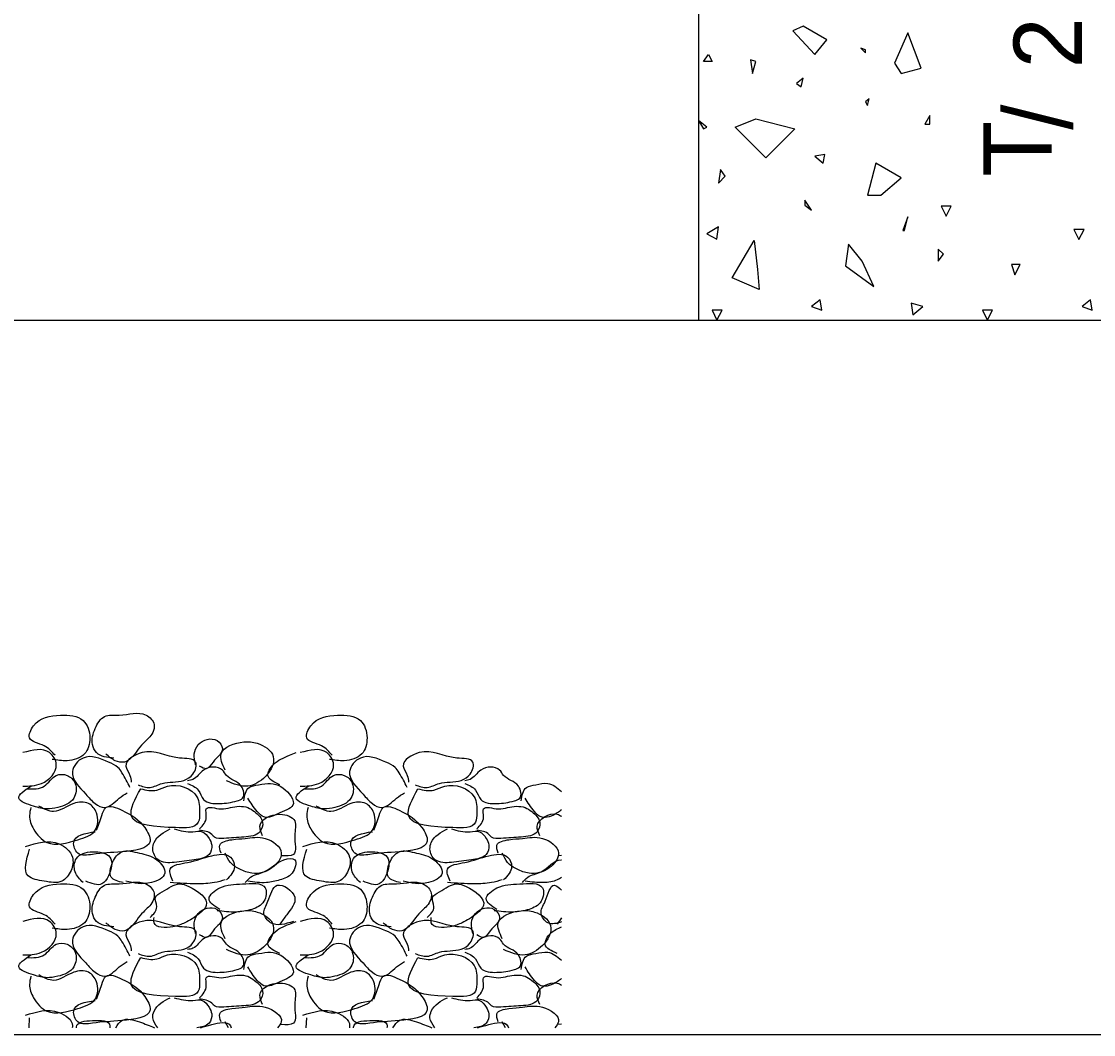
# Model space of a CAD drawing. Extents: x 2.92 to 10.05, y 1.3 to 10.63.
# Drawn here: x 5.007 to 5.949, y 5.922 to 6.811 of the extents above; entities that cross this region are included whole.
import ezdxf

# ---------------------------------------------------------------- set-up
doc = ezdxf.new("R2010")
doc.units = 0
for name, color, linetype in [('DETL-LINE', 7, 'Continuous'), ('DETL-NOTE', 7, 'Continuous'), ('DETL-PATT', 7, 'Continuous')]:
    doc.layers.add(name, color=color, linetype=linetype)

msp = doc.modelspace()

# ---------------------------------------------------------------- linework, layer by layer
at = {"layer": 'DETL-LINE'}
for p, q in [((5.60141, 7.37627), (5.60141, 6.54902)), ((3.60141, 6.54902), (7.87612, 6.54902)), ((3.60141, 5.92157), (7.87612, 5.92157))]:
    msp.add_line(p, q, dxfattribs=at)
at = {"layer": 'DETL-PATT'}
for p, q in [((5.48133, 6.0789), (5.47859, 6.07859)), ((5.48133, 6.02408), (5.47741, 6.01859)), ((5.01345, 5.92761), (5.01388, 5.93624)), ((5.25698, 5.92761), (5.25741, 5.93624)), ((5.18855, 5.92761), (5.18565, 5.93271)), ((5.43208, 5.92761), (5.42918, 5.93271)), ((5.48133, 5.93067), (5.47859, 5.93035))]:
    msp.add_line(p, q, dxfattribs=at)
for points in [[(5.68435, 6.80314), (5.70376, 6.78231), (5.71435, 6.79537), (5.69353, 6.80737)], [(5.77965, 6.76573), (5.79729, 6.77031), (5.78529, 6.80137), (5.77365, 6.7749)], [(5.61024, 6.78231), (5.61341, 6.77631), (5.606, 6.77631)], [(5.74824, 6.78655), (5.744, 6.78796), (5.74824, 6.78373)], [(5.64729, 6.77773), (5.64906, 6.76573), (5.65188, 6.77631)], [(5.68753, 6.7569), (5.69176, 6.75408), (5.69353, 6.76149)], [(5.75141, 6.74349), (5.74824, 6.74067), (5.75, 6.73749)], [(5.65188, 6.72584), (5.68612, 6.71702), (5.66071, 6.69161), (5.63388, 6.71843)], [(5.80471, 6.72867), (5.80047, 6.72125), (5.80471, 6.72125)], [(5.70376, 6.69302), (5.71118, 6.68702), (5.71259, 6.69443)], [(5.76165, 6.65878), (5.77965, 6.67396), (5.75741, 6.68702), (5.75, 6.65878)], [(5.62082, 6.68137), (5.61906, 6.66937), (5.62506, 6.67537)], [(5.69494, 6.65455), (5.69494, 6.64996), (5.70094, 6.64573)], [(5.81473, 6.64912), (5.81897, 6.64029), (5.82356, 6.64912)], [(5.60882, 6.6249), (5.61765, 6.62031), (5.61906, 6.6309)], [(5.78106, 6.62773), (5.78247, 6.62773), (5.78529, 6.63973)], [(5.93139, 6.62876), (5.93563, 6.61994), (5.94022, 6.62876)], [(5.65329, 6.59349), (5.65471, 6.57584), (5.63106, 6.58608), (5.65047, 6.6189)], [(5.73341, 6.61573), (5.73059, 6.59667), (5.75565, 6.57867), (5.74541, 6.6009)], [(5.81212, 6.61149), (5.81212, 6.6009), (5.81671, 6.6069)], [(5.87658, 6.59781), (5.8794, 6.58899), (5.88399, 6.59781)], [(5.70835, 6.56702), (5.70094, 6.56102), (5.70976, 6.55784)], [(5.94588, 6.56702), (5.93847, 6.56102), (5.94729, 6.55784)], [(5.78847, 6.56384), (5.78988, 6.55361), (5.79871, 6.56102)]]:
    msp.add_lwpolyline(points, close=True, dxfattribs=at)
for points in [[(5.60141, 6.72443), (5.606, 6.71702), (5.60882, 6.71843), (5.60141, 6.72443)], [(5.61765, 6.54902), (5.62224, 6.55784), (5.61341, 6.55784), (5.61765, 6.54902)], [(5.85533, 6.54929), (5.85976, 6.55784), (5.85094, 6.55784), (5.85506, 6.54929)]]:
    msp.add_lwpolyline(points, dxfattribs=at)
for points in [[(5.03624, 6.16682), (5.02682, 6.17506), (5.01388, 6.18212), (5.01741, 6.19271), (5.04094, 6.20212), (5.06094, 6.19741), (5.06682, 6.18212), (5.06212, 6.168), (5.04682, 6.16212), (5.03388, 6.16329)], [(5.088, 6.16447), (5.07271, 6.16918), (5.06918, 6.17624), (5.07153, 6.19035), (5.07976, 6.20094), (5.09271, 6.20212), (5.11624, 6.20212), (5.12329, 6.19388), (5.12212, 6.18682), (5.11388, 6.17741), (5.108, 6.17035), (5.09741, 6.16094), (5.08918, 6.16212), (5.08094, 6.168)], [(5.27976, 6.16682), (5.27035, 6.17506), (5.25741, 6.18212), (5.26094, 6.19271), (5.28447, 6.20212), (5.30447, 6.19741), (5.31035, 6.18212), (5.30565, 6.168), (5.29035, 6.16212), (5.27741, 6.16329)], [(5.15976, 6.15859), (5.15859, 6.168), (5.16212, 6.17624), (5.17859, 6.17976), (5.18329, 6.17271), (5.17506, 6.16094), (5.16918, 6.15506), (5.16329, 6.15741)], [(5.18565, 6.15388), (5.18212, 6.168), (5.20212, 6.17859), (5.21388, 6.17741), (5.228, 6.16565), (5.22682, 6.15624), (5.22094, 6.148), (5.20565, 6.13976), (5.18682, 6.14447)], [(5.008, 6.13976), (5.02447, 6.14212), (5.03741, 6.15859), (5.03153, 6.16918), (5.008, 6.16918)], [(5.10918, 6.14094), (5.11976, 6.13859), (5.13035, 6.14212), (5.13976, 6.14329), (5.15741, 6.15035), (5.15976, 6.16094), (5.14565, 6.16447), (5.11271, 6.16918), (5.09859, 6.15741), (5.10212, 6.14918), (5.10329, 6.14329)], [(5.23388, 6.14094), (5.22329, 6.14918), (5.228, 6.15859), (5.24212, 6.16682), (5.248, 6.16918)], [(5.25153, 6.13976), (5.268, 6.14212), (5.28094, 6.15859), (5.27506, 6.16918), (5.25153, 6.16918)], [(5.35271, 6.14094), (5.36329, 6.13859), (5.37388, 6.14212), (5.38329, 6.14329), (5.40094, 6.15035), (5.40329, 6.16094), (5.38918, 6.16447), (5.35624, 6.16918), (5.34212, 6.15741), (5.34565, 6.14918), (5.34682, 6.14329)], [(5.10212, 6.13859), (5.09506, 6.15153), (5.09153, 6.15624), (5.08329, 6.16094), (5.06094, 6.16447), (5.05153, 6.15271), (5.06329, 6.13271), (5.07153, 6.12447), (5.07976, 6.12094), (5.09271, 6.12918), (5.09976, 6.13388)], [(5.34565, 6.13859), (5.33859, 6.15153), (5.33506, 6.15624), (5.32682, 6.16094), (5.30447, 6.16447), (5.29506, 6.15271), (5.30682, 6.13271), (5.31506, 6.12447), (5.32329, 6.12094), (5.33624, 6.12918), (5.34329, 6.13388)], [(5.01153, 6.13741), (5.02682, 6.13976), (5.03741, 6.14918), (5.04682, 6.14918), (5.05388, 6.14212), (5.05271, 6.12918), (5.03859, 6.12094), (5.02918, 6.11976), (5.01741, 6.12212), (5.00447, 6.12918), (5.01506, 6.13976)], [(5.15271, 6.14212), (5.16212, 6.13624), (5.16682, 6.128), (5.18094, 6.12447), (5.19624, 6.12682), (5.20094, 6.12918), (5.19976, 6.13976), (5.18682, 6.14918), (5.18329, 6.15388), (5.16682, 6.15388), (5.15741, 6.14565), (5.15271, 6.14447)], [(5.25506, 6.13741), (5.27035, 6.13976), (5.28094, 6.14918), (5.29035, 6.14918), (5.29741, 6.14212), (5.29624, 6.12918), (5.28212, 6.12094), (5.27271, 6.11976), (5.26094, 6.12212), (5.248, 6.12918), (5.25859, 6.13976)], [(5.39624, 6.14212), (5.40565, 6.13624), (5.41035, 6.128), (5.42447, 6.12447), (5.43976, 6.12682), (5.44447, 6.12918), (5.44329, 6.13976), (5.43035, 6.14918), (5.42682, 6.15388), (5.41035, 6.15388), (5.40094, 6.14565), (5.39624, 6.14447)], [(5.11153, 6.13741), (5.10329, 6.11388), (5.14212, 6.10329), (5.16212, 6.108), (5.16329, 6.11624), (5.16094, 6.13035), (5.13506, 6.13976), (5.12565, 6.13624), (5.11153, 6.13741)], [(5.20212, 6.12682), (5.20682, 6.13859), (5.21506, 6.14094), (5.22565, 6.14212), (5.24212, 6.13271), (5.24565, 6.12447), (5.23388, 6.11624), (5.21976, 6.11271), (5.21388, 6.11741), (5.20565, 6.12918)], [(5.35506, 6.13741), (5.34682, 6.11388), (5.38565, 6.10329), (5.40565, 6.108), (5.40682, 6.11624), (5.40447, 6.13035), (5.37859, 6.13976), (5.36918, 6.13624), (5.35506, 6.13741)], [(5.44565, 6.12682), (5.45035, 6.13859), (5.45859, 6.14094), (5.46918, 6.14212), (5.48133, 6.13518)], [(5.01506, 6.12094), (5.01388, 6.11388), (5.01741, 6.10212), (5.02918, 6.09035), (5.05624, 6.09271), (5.07153, 6.10094), (5.07271, 6.11624), (5.06565, 6.12447), (5.05271, 6.12447), (5.03506, 6.11741), (5.02212, 6.12212)], [(5.07271, 6.10094), (5.07741, 6.11388), (5.08094, 6.12094), (5.09506, 6.11859), (5.11506, 6.10329), (5.11976, 6.09153), (5.09506, 6.08212), (5.06918, 6.07976), (5.05624, 6.08094), (5.05271, 6.09035), (5.07153, 6.09976)], [(5.16329, 6.10212), (5.16918, 6.11271), (5.16918, 6.11976), (5.18212, 6.11976), (5.19035, 6.12094), (5.20565, 6.12094), (5.21153, 6.11741), (5.21859, 6.108), (5.21624, 6.09976), (5.21035, 6.09624), (5.20212, 6.09506), (5.18447, 6.09388), (5.17624, 6.09506), (5.17388, 6.09741), (5.16329, 6.10094)], [(5.25859, 6.12094), (5.25741, 6.11388), (5.26094, 6.10212), (5.27271, 6.09035), (5.29976, 6.09271), (5.31506, 6.10094), (5.31624, 6.11624), (5.30918, 6.12447), (5.29624, 6.12447), (5.27859, 6.11741), (5.26565, 6.12212)], [(5.31624, 6.10094), (5.32094, 6.11388), (5.32447, 6.12094), (5.33859, 6.11859), (5.35859, 6.10329), (5.36329, 6.09153), (5.33859, 6.08212), (5.31271, 6.07976), (5.29976, 6.08094), (5.29624, 6.09035), (5.31506, 6.09976)], [(5.40682, 6.10212), (5.41271, 6.11271), (5.41271, 6.11976), (5.42565, 6.11976), (5.43388, 6.12094), (5.44918, 6.12094), (5.45506, 6.11741), (5.46212, 6.108), (5.45976, 6.09976), (5.45388, 6.09624), (5.44565, 6.09506), (5.428, 6.09388), (5.41976, 6.09506), (5.41741, 6.09741), (5.40682, 6.10094)], [(5.48133, 6.11898), (5.47741, 6.11624), (5.46329, 6.11271), (5.45741, 6.11741), (5.44918, 6.12918)], [(5.21859, 6.09624), (5.21624, 6.10447), (5.23388, 6.11506), (5.24682, 6.10918), (5.24682, 6.09624), (5.24565, 6.07976), (5.23506, 6.07859)], [(5.46212, 6.09624), (5.45976, 6.10447), (5.47741, 6.11506), (5.48133, 6.11329)], [(5.14094, 6.10212), (5.15741, 6.09976), (5.16565, 6.09976), (5.17153, 6.09388), (5.17388, 6.088), (5.17153, 6.07976), (5.15859, 6.07506), (5.14094, 6.07271), (5.12682, 6.07506), (5.12212, 6.08447), (5.12329, 6.09035), (5.12918, 6.09741), (5.13741, 6.10212)], [(5.18212, 6.08094), (5.18094, 6.088), (5.19153, 6.09271), (5.20329, 6.09388), (5.22094, 6.09388), (5.23506, 6.08094), (5.22682, 6.068), (5.20918, 6.06329), (5.19859, 6.06682), (5.19035, 6.07271), (5.18565, 6.08094)], [(5.38447, 6.10212), (5.40094, 6.09976), (5.40918, 6.09976), (5.41506, 6.09388), (5.41741, 6.088), (5.41506, 6.07976), (5.40212, 6.07506), (5.38447, 6.07271), (5.37035, 6.07506), (5.36565, 6.08447), (5.36682, 6.09035), (5.37271, 6.09741), (5.38094, 6.10212)], [(5.42565, 6.08094), (5.42447, 6.088), (5.43506, 6.09271), (5.44682, 6.09388), (5.46447, 6.09388), (5.47859, 6.08094), (5.47035, 6.068), (5.45271, 6.06329), (5.44212, 6.06682), (5.43388, 6.07271), (5.42918, 6.08094)], [(5.01035, 6.08682), (5.03976, 6.08918), (5.05153, 6.07741), (5.05035, 6.06565), (5.04212, 6.05624), (5.02682, 6.05624), (5.01271, 6.06094), (5.01388, 6.08447)], [(5.25388, 6.08682), (5.28329, 6.08918), (5.29506, 6.07741), (5.29388, 6.06565), (5.28565, 6.05624), (5.27035, 6.05624), (5.25624, 6.06094), (5.25741, 6.08447)], [(5.06094, 6.05506), (5.05388, 6.06447), (5.05506, 6.07624), (5.06918, 6.08212), (5.08447, 6.07741), (5.08329, 6.06094), (5.07741, 6.05388), (5.06329, 6.05624)], [(5.09624, 6.05506), (5.08565, 6.05976), (5.08682, 6.07271), (5.09506, 6.08212), (5.11035, 6.08094), (5.12565, 6.07506), (5.13271, 6.06329), (5.12094, 6.05506), (5.09859, 6.05624)], [(5.13976, 6.05624), (5.13741, 6.06682), (5.15271, 6.07271), (5.17388, 6.07859), (5.19035, 6.07741), (5.19388, 6.06918), (5.18682, 6.05741)], [(5.20329, 6.05506), (5.208, 6.05976), (5.21976, 6.06447), (5.23741, 6.07506), (5.24682, 6.07506), (5.24447, 6.06329), (5.23388, 6.05741), (5.22212, 6.05506), (5.20565, 6.05624)], [(5.30447, 6.05506), (5.29741, 6.06447), (5.29859, 6.07624), (5.31271, 6.08212), (5.328, 6.07741), (5.32682, 6.06094), (5.32094, 6.05388), (5.30682, 6.05624)], [(5.33976, 6.05506), (5.32918, 6.05976), (5.33035, 6.07271), (5.33859, 6.08212), (5.35388, 6.08094), (5.36918, 6.07506), (5.37624, 6.06329), (5.36447, 6.05506), (5.34212, 6.05624)], [(5.38329, 6.05624), (5.38094, 6.06682), (5.39624, 6.07271), (5.41741, 6.07859), (5.43388, 6.07741), (5.43741, 6.06918), (5.43035, 6.05741)], [(5.44682, 6.05506), (5.45153, 6.05976), (5.46329, 6.06447), (5.48094, 6.07506), (5.48133, 6.07506)], [(5.088, 6.01624), (5.07271, 6.02094), (5.06918, 6.028), (5.07153, 6.04212), (5.07976, 6.05271), (5.09271, 6.05388), (5.11624, 6.05388), (5.12329, 6.04565), (5.12212, 6.03859), (5.11388, 6.02918), (5.108, 6.02212), (5.09741, 6.01271), (5.08918, 6.01388), (5.08094, 6.01976)], [(5.18565, 6.05741), (5.17624, 6.05506), (5.16094, 6.05388), (5.13741, 6.05506)], [(5.33153, 6.01624), (5.31624, 6.02094), (5.31271, 6.028), (5.31506, 6.04212), (5.32329, 6.05271), (5.33624, 6.05388), (5.35976, 6.05388), (5.36682, 6.04565), (5.36565, 6.03859), (5.35741, 6.02918), (5.35153, 6.02212), (5.34094, 6.01271), (5.33271, 6.01388), (5.32447, 6.01976)], [(5.42918, 6.05741), (5.41976, 6.05506), (5.40447, 6.05388), (5.38094, 6.05506)], [(5.48133, 6.05961), (5.47741, 6.05741), (5.46565, 6.05506), (5.44918, 6.05624)], [(5.03624, 6.01859), (5.02682, 6.02682), (5.01388, 6.03388), (5.01741, 6.04447), (5.04094, 6.05388), (5.06094, 6.04918), (5.06682, 6.03388), (5.06212, 6.01976), (5.04682, 6.01388), (5.03388, 6.01506)], [(5.11976, 6.02447), (5.12565, 6.03388), (5.12447, 6.04212), (5.13035, 6.04682), (5.14565, 6.05388), (5.15388, 6.05153), (5.16918, 6.03506), (5.16329, 6.028), (5.15035, 6.01976), (5.13976, 6.01624), (5.12329, 6.01976), (5.12329, 6.02447)], [(5.18094, 6.03153), (5.17153, 6.04094), (5.18094, 6.05035), (5.20094, 6.05388), (5.22094, 6.05035), (5.21976, 6.03859), (5.20918, 6.03153), (5.19506, 6.02918), (5.17859, 6.03035)], [(5.24565, 6.02094), (5.22565, 6.01976), (5.21976, 6.028), (5.22329, 6.03859), (5.23153, 6.05271), (5.24682, 6.04212), (5.23976, 6.02682), (5.23388, 6.01859)], [(5.27976, 6.01859), (5.27035, 6.02682), (5.25741, 6.03388), (5.26094, 6.04447), (5.28447, 6.05388), (5.30447, 6.04918), (5.31035, 6.03388), (5.30565, 6.01976), (5.29035, 6.01388), (5.27741, 6.01506)], [(5.36329, 6.02447), (5.36918, 6.03388), (5.368, 6.04212), (5.37388, 6.04682), (5.38918, 6.05388), (5.39741, 6.05153), (5.41271, 6.03506), (5.40682, 6.028), (5.39388, 6.01976), (5.38329, 6.01624), (5.36682, 6.01976), (5.36682, 6.02447)], [(5.42447, 6.03153), (5.41506, 6.04094), (5.42447, 6.05035), (5.44447, 6.05388), (5.46447, 6.05035), (5.46329, 6.03859), (5.45271, 6.03153), (5.43859, 6.02918), (5.42212, 6.03035)], [(5.48133, 6.02047), (5.46918, 6.01976), (5.46329, 6.028), (5.46682, 6.03859), (5.47506, 6.05271), (5.48133, 6.04835)], [(5.15976, 6.01035), (5.15859, 6.01976), (5.16212, 6.028), (5.17859, 6.03153), (5.18329, 6.02447), (5.17506, 6.01271), (5.16918, 6.00682), (5.16329, 6.00918)], [(5.18565, 6.00565), (5.18212, 6.01976), (5.20212, 6.03035), (5.21388, 6.02918), (5.228, 6.01741), (5.22682, 6.008), (5.22094, 5.99976), (5.20565, 5.99153), (5.18682, 5.99624)], [(5.40329, 6.01035), (5.40212, 6.01976), (5.40565, 6.028), (5.42212, 6.03153), (5.42682, 6.02447), (5.41859, 6.01271), (5.41271, 6.00682), (5.40682, 6.00918)], [(5.42918, 6.00565), (5.42565, 6.01976), (5.44565, 6.03035), (5.45741, 6.02918), (5.47153, 6.01741), (5.47035, 6.008), (5.46447, 5.99976), (5.44918, 5.99153), (5.43035, 5.99624)], [(5.008, 5.99153), (5.02447, 5.99388), (5.03741, 6.01035), (5.03153, 6.02094), (5.008, 6.02094)], [(5.10212, 5.99035), (5.09506, 6.00329), (5.09153, 6.008), (5.08329, 6.01271), (5.06094, 6.01624), (5.05153, 6.00447), (5.06329, 5.98447), (5.07153, 5.97624), (5.07976, 5.97271), (5.09271, 5.98094), (5.09976, 5.98565)], [(5.10918, 5.99271), (5.11976, 5.99035), (5.13035, 5.99388), (5.13976, 5.99506), (5.15741, 6.00212), (5.15976, 6.01271), (5.14565, 6.01624), (5.11271, 6.02094), (5.09859, 6.00918), (5.10212, 6.00094), (5.10329, 5.99506)], [(5.23388, 5.99271), (5.22329, 6.00094), (5.228, 6.01035), (5.24212, 6.01859), (5.248, 6.02094)], [(5.25153, 5.99153), (5.268, 5.99388), (5.28094, 6.01035), (5.27506, 6.02094), (5.25153, 6.02094)], [(5.34565, 5.99035), (5.33859, 6.00329), (5.33506, 6.008), (5.32682, 6.01271), (5.30447, 6.01624), (5.29506, 6.00447), (5.30682, 5.98447), (5.31506, 5.97624), (5.32329, 5.97271), (5.33624, 5.98094), (5.34329, 5.98565)], [(5.35271, 5.99271), (5.36329, 5.99035), (5.37388, 5.99388), (5.38329, 5.99506), (5.40094, 6.00212), (5.40329, 6.01271), (5.38918, 6.01624), (5.35624, 6.02094), (5.34212, 6.00918), (5.34565, 6.00094), (5.34682, 5.99506)], [(5.15271, 5.99388), (5.16212, 5.988), (5.16682, 5.97976), (5.18094, 5.97624), (5.19624, 5.97859), (5.20094, 5.98094), (5.19976, 5.99153), (5.18682, 6.00094), (5.18329, 6.00565), (5.16682, 6.00565), (5.15741, 5.99741), (5.15271, 5.99624)], [(5.39624, 5.99388), (5.40565, 5.988), (5.41035, 5.97976), (5.42447, 5.97624), (5.43976, 5.97859), (5.44447, 5.98094), (5.44329, 5.99153), (5.43035, 6.00094), (5.42682, 6.00565), (5.41035, 6.00565), (5.40094, 5.99741), (5.39624, 5.99624)], [(5.47741, 5.99271), (5.46682, 6.00094), (5.47153, 6.01035), (5.48133, 6.01608)], [(5.01153, 5.98918), (5.02682, 5.99153), (5.03741, 6.00094), (5.04682, 6.00094), (5.05388, 5.99388), (5.05271, 5.98094), (5.03859, 5.97271), (5.02918, 5.97153), (5.01741, 5.97388), (5.00447, 5.98094), (5.01506, 5.99153)], [(5.25506, 5.98918), (5.27035, 5.99153), (5.28094, 6.00094), (5.29035, 6.00094), (5.29741, 5.99388), (5.29624, 5.98094), (5.28212, 5.97271), (5.27271, 5.97153), (5.26094, 5.97388), (5.248, 5.98094), (5.25859, 5.99153)], [(5.11153, 5.98918), (5.10329, 5.96565), (5.14212, 5.95506), (5.16212, 5.95976), (5.16329, 5.968), (5.16094, 5.98212), (5.13506, 5.99153), (5.12565, 5.988), (5.11153, 5.98918)], [(5.20212, 5.97859), (5.20682, 5.99035), (5.21506, 5.99271), (5.22565, 5.99388), (5.24212, 5.98447), (5.24565, 5.97624), (5.23388, 5.968), (5.21976, 5.96447), (5.21388, 5.96918), (5.20565, 5.98094)], [(5.35506, 5.98918), (5.34682, 5.96565), (5.38565, 5.95506), (5.40565, 5.95976), (5.40682, 5.968), (5.40447, 5.98212), (5.37859, 5.99153), (5.36918, 5.988), (5.35506, 5.98918)], [(5.44565, 5.97859), (5.45035, 5.99035), (5.45859, 5.99271), (5.46918, 5.99388), (5.48133, 5.98694)], [(5.48133, 5.97075), (5.47741, 5.968), (5.46329, 5.96447), (5.45741, 5.96918), (5.44918, 5.98094)], [(5.01506, 5.97271), (5.01388, 5.96565), (5.01741, 5.95388), (5.02918, 5.94212), (5.05624, 5.94447), (5.07153, 5.95271), (5.07271, 5.968), (5.06565, 5.97624), (5.05271, 5.97624), (5.03506, 5.96918), (5.02212, 5.97388)], [(5.07271, 5.95271), (5.07741, 5.96565), (5.08094, 5.97271), (5.09506, 5.97035), (5.11506, 5.95506), (5.11976, 5.94329), (5.09506, 5.93388), (5.06918, 5.93153), (5.05624, 5.93271), (5.05271, 5.94212), (5.07153, 5.95153)], [(5.16329, 5.95388), (5.16918, 5.96447), (5.16918, 5.97153), (5.18212, 5.97153), (5.19035, 5.97271), (5.20565, 5.97271), (5.21153, 5.96918), (5.21859, 5.95976), (5.21624, 5.95153), (5.21035, 5.948), (5.20212, 5.94682), (5.18447, 5.94565), (5.17624, 5.94682), (5.17388, 5.94918), (5.16329, 5.95271)], [(5.25859, 5.97271), (5.25741, 5.96565), (5.26094, 5.95388), (5.27271, 5.94212), (5.29976, 5.94447), (5.31506, 5.95271), (5.31624, 5.968), (5.30918, 5.97624), (5.29624, 5.97624), (5.27859, 5.96918), (5.26565, 5.97388)], [(5.31624, 5.95271), (5.32094, 5.96565), (5.32447, 5.97271), (5.33859, 5.97035), (5.35859, 5.95506), (5.36329, 5.94329), (5.33859, 5.93388), (5.31271, 5.93153), (5.29976, 5.93271), (5.29624, 5.94212), (5.31506, 5.95153)], [(5.40682, 5.95388), (5.41271, 5.96447), (5.41271, 5.97153), (5.42565, 5.97153), (5.43388, 5.97271), (5.44918, 5.97271), (5.45506, 5.96918), (5.46212, 5.95976), (5.45976, 5.95153), (5.45388, 5.948), (5.44565, 5.94682), (5.428, 5.94565), (5.41976, 5.94682), (5.41741, 5.94918), (5.40682, 5.95271)], [(5.21859, 5.948), (5.21624, 5.95624), (5.23388, 5.96682), (5.24682, 5.96094), (5.24682, 5.948), (5.24565, 5.93153), (5.23506, 5.93035)], [(5.46212, 5.948), (5.45976, 5.95624), (5.47741, 5.96682), (5.48133, 5.96506)], [(5.12643, 5.92761), (5.12212, 5.93624), (5.12329, 5.94212), (5.12918, 5.94918), (5.13741, 5.95388)], [(5.14094, 5.95388), (5.15741, 5.95153), (5.16565, 5.95153), (5.17153, 5.94565), (5.17388, 5.93976), (5.17153, 5.93153), (5.16075, 5.92761)], [(5.36996, 5.92761), (5.36565, 5.93624), (5.36682, 5.94212), (5.37271, 5.94918), (5.38094, 5.95388)], [(5.38447, 5.95388), (5.40094, 5.95153), (5.40918, 5.95153), (5.41506, 5.94565), (5.41741, 5.93976), (5.41506, 5.93153), (5.40427, 5.92761)], [(5.01035, 5.93859), (5.03976, 5.94094), (5.05153, 5.92918), (5.05137, 5.92761)], [(5.18212, 5.93271), (5.18094, 5.93976), (5.19153, 5.94447), (5.20329, 5.94565), (5.22094, 5.94565), (5.23506, 5.93271), (5.2318, 5.92761)], [(5.25388, 5.93859), (5.28329, 5.94094), (5.29506, 5.92918), (5.2949, 5.92761)], [(5.42565, 5.93271), (5.42447, 5.93976), (5.43506, 5.94447), (5.44682, 5.94565), (5.46447, 5.94565), (5.47859, 5.93271), (5.47533, 5.92761)], [(5.05502, 5.92761), (5.05506, 5.928), (5.06918, 5.93388), (5.08447, 5.92918), (5.08435, 5.92761)], [(5.08957, 5.92761), (5.09506, 5.93388), (5.11035, 5.93271), (5.12361, 5.92761)], [(5.164, 5.92761), (5.17388, 5.93035), (5.19035, 5.92918), (5.19102, 5.92761)], [(5.29855, 5.92761), (5.29859, 5.928), (5.31271, 5.93388), (5.328, 5.92918), (5.32788, 5.92761)], [(5.3331, 5.92761), (5.33859, 5.93388), (5.35388, 5.93271), (5.36714, 5.92761)], [(5.40753, 5.92761), (5.41741, 5.93035), (5.43388, 5.92918), (5.43455, 5.92761)]]:
    msp.add_spline(points, degree=3, dxfattribs=at)

# ---------------------------------------------------------------- texts
at = {"layer": 'DETL-NOTE'}
for s, p in [('2', (5.93836, 6.77025)), ('/', (5.92988, 6.71619)), ('T', (5.91189, 6.67512))]:
    msp.add_text(s, height=0.06, rotation=90, dxfattribs=at).set_placement(p)

doc.saveas('drawing.dxf')
